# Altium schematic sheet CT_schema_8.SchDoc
size 367 x 245 mm
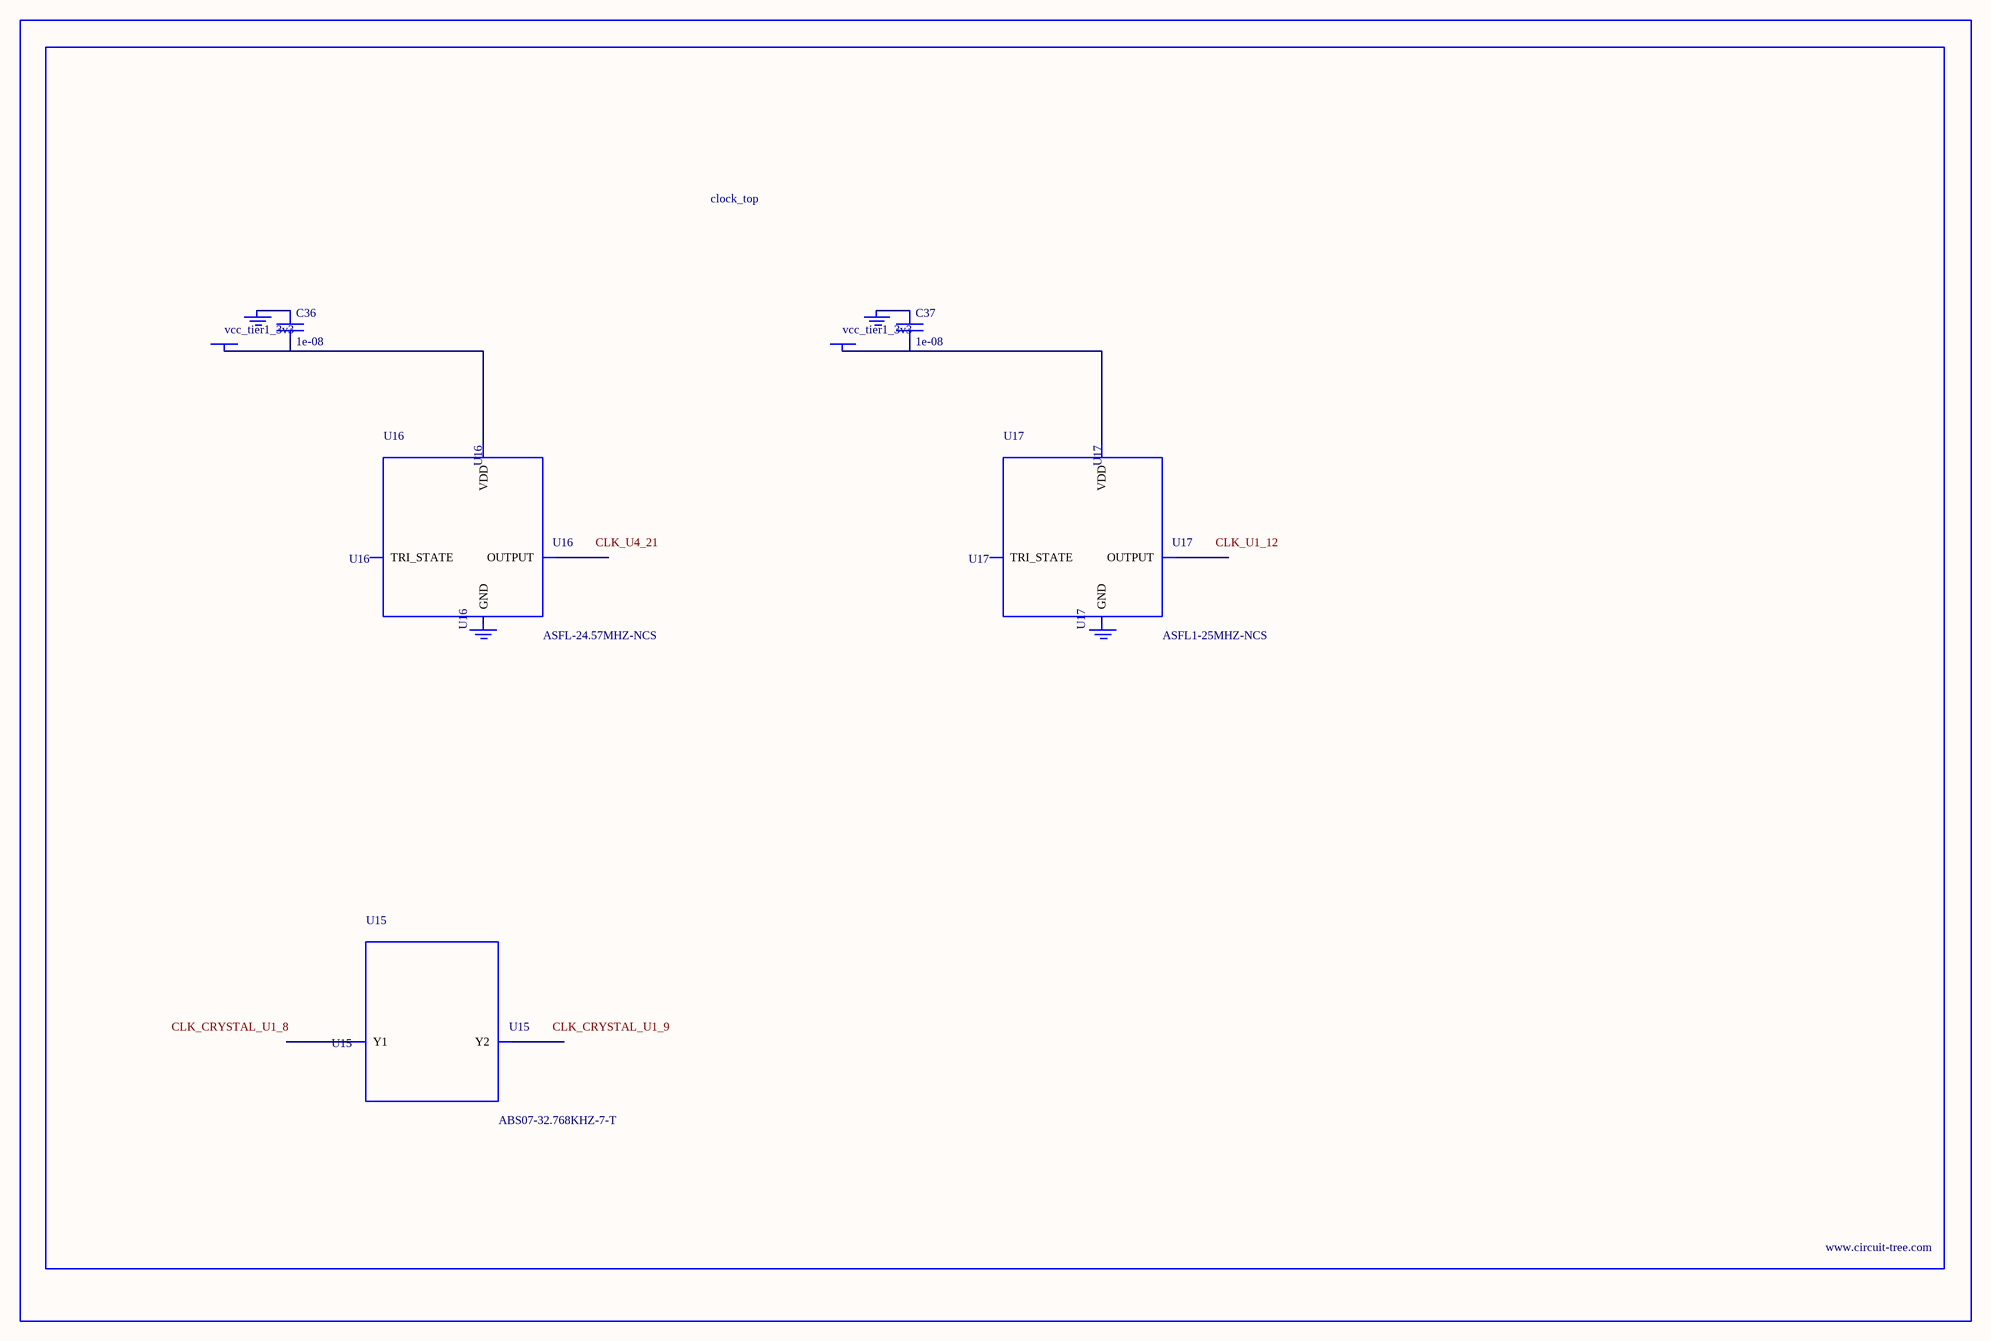
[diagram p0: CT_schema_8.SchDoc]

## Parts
BORDER7  (no value)
C36  1e-08  [C0402]
C37  1e-08  [C0402]
GND_INSTANCE_7_0  (no value)
GND_INSTANCE_7_1  (no value)
GND_INSTANCE_7_2  (no value)
GND_INSTANCE_7_3  (no value)
POWER_INSTANCE_7_0  vcc_tier1_3v3
POWER_INSTANCE_7_1  vcc_tier1_3v3
U15  ABS07-32.768KHZ-7-T  [ABS07-32.768KHZ-7-T]
U16  ASFL-24.57MHZ-NCS  [ASFL1]
U17  ASFL1-25MHZ-NCS  [ASFL1]

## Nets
NetC36_1: C36.1 GND_INSTANCE_7_0.0(GND)
NetC36_2: C36.2 POWER_INSTANCE_7_0.0(PWR) U16.4(VDD)
NetC37_1: C37.1 GND_INSTANCE_7_2.0(GND)
NetC37_2: C37.2 POWER_INSTANCE_7_1.0(PWR) U17.4(VDD)

Not connected (* = marked no-connect by the designer): GND_INSTANCE_7_1 0(GND); GND_INSTANCE_7_3 0(GND); U15 1(Y1) 2(Y2); U16 1(TRI_STATE) 2(GND) 3(OUTPUT); U17 1(TRI_STATE) 2(GND) 3(OUTPUT)

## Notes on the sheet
- Labels drawn without touching a wire or pin: CLK_CRYSTAL_U1_8, CLK_CRYSTAL_U1_9, CLK_U1_12, CLK_U4_21

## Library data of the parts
BORDER7 = BORDER_PAGE7
C36 C37 = C0402C103K3RAC
GND_INSTANCE_7_0-GND_INSTANCE_7_3 = GND
POWER_INSTANCE_7_0 POWER_INSTANCE_7_1 = PWR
